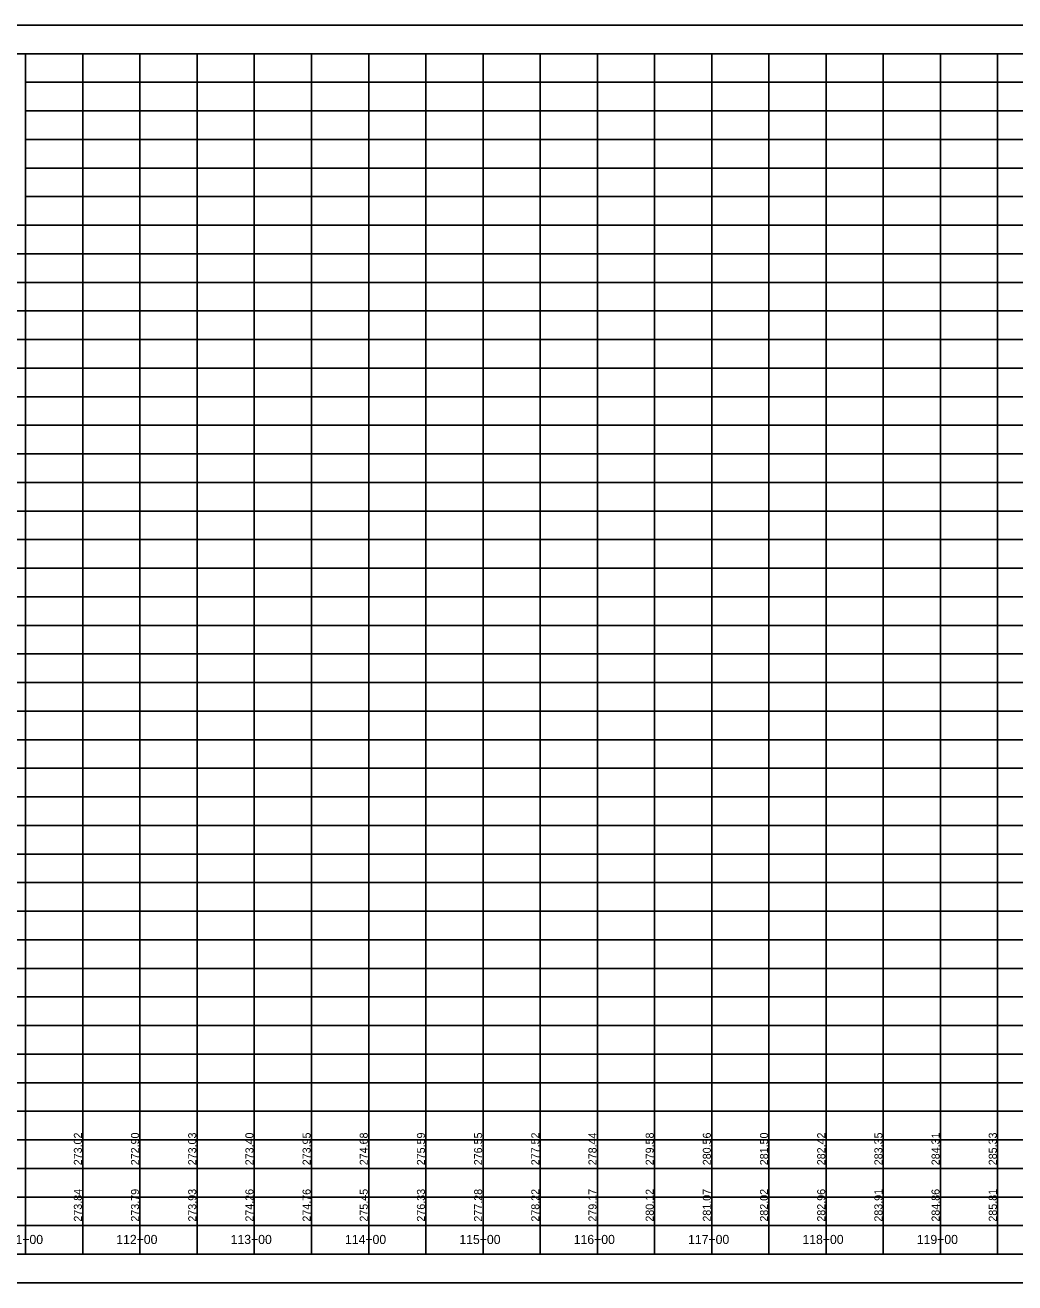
# Model space of a CAD drawing. Extents: x 1873632 to 1926512, y 813126 to 836257.
# Drawn here: x 1889463 to 1890328, y 828463 to 829563 of the extents above; entities that cross this region are included whole.
import ezdxf

# ---------------------------------------------------------------- set-up
doc = ezdxf.new("R2010")
doc.units = 0
for name, color, linetype in [('RD_DDB_StaTX', 7, 'Continuous'), ('RD_DDB_StripGrade', 7, 'Continuous'), ('RD_PD_WallFill', 7, 'Continuous'), ('RD_SHT_IplotShp', 7, 'Continuous')]:
    doc.layers.add(name, color=color, linetype=linetype)

msp = doc.modelspace()

# ---------------------------------------------------------------- linework, layer by layer
at = {"layer": 'RD_PD_WallFill'}
for p, q in [((1889012.9, 829538.1), (1894362.9, 829538.1)), ((1889012.9, 829538.1), (1890762.9, 829538.1)), ((1889462.9, 828488.1), (1889462.9, 829538.1)), ((1889462.9, 828488.1), (1889462.9, 829538.1)), ((1889512.9, 828488.1), (1889512.9, 829538.1)), ((1889512.9, 828488.1), (1889512.9, 829538.1)), ((1889562.9, 828488.1), (1889562.9, 829538.1)), ((1889562.9, 828488.1), (1889562.9, 829538.1)), ((1889612.9, 828488.1), (1889612.9, 829538.1)), ((1889612.9, 828488.1), (1889612.9, 829538.1)), ((1889662.9, 828488.1), (1889662.9, 829538.1)), ((1889662.9, 828488.1), (1889662.9, 829538.1)), ((1889712.9, 828488.1), (1889712.9, 829538.1)), ((1889712.9, 828488.1), (1889712.9, 829538.1)), ((1889762.9, 828488.1), (1889762.9, 829538.1)), ((1889762.9, 828488.1), (1889762.9, 829538.1)), ((1889812.9, 828488.1), (1889812.9, 829538.1)), ((1889812.9, 828488.1), (1889812.9, 829538.1)), ((1889862.9, 828488.1), (1889862.9, 829538.1)), ((1889862.9, 828488.1), (1889862.9, 829538.1)), ((1889912.9, 828488.1), (1889912.9, 829538.1)), ((1889912.9, 828488.1), (1889912.9, 829538.1)), ((1889962.9, 828488.1), (1889962.9, 829538.1)), ((1889962.9, 828488.1), (1889962.9, 829538.1)), ((1890012.9, 828488.1), (1890012.9, 829538.1)), ((1890012.9, 828488.1), (1890012.9, 829538.1)), ((1890062.9, 828488.1), (1890062.9, 829538.1)), ((1890062.9, 828488.1), (1890062.9, 829538.1)), ((1890112.9, 828488.1), (1890112.9, 829538.1)), ((1890112.9, 828488.1), (1890112.9, 829538.1)), ((1890162.9, 828488.1), (1890162.9, 829538.1)), ((1890162.9, 828488.1), (1890162.9, 829538.1)), ((1890212.9, 828488.1), (1890212.9, 829538.1)), ((1890212.9, 828488.1), (1890212.9, 829538.1)), ((1890262.9, 828488.1), (1890262.9, 829538.1)), ((1890262.9, 828488.1), (1890262.9, 829538.1)), ((1890312.9, 828488.1), (1890312.9, 829538.1)), ((1890312.9, 828488.1), (1890312.9, 829538.1)), ((1889462.9, 829513.1), (1894362.9, 829513.1)), ((1889462.9, 829513.1), (1894362.9, 829513.1)), ((1889462.9, 829488.1), (1894362.9, 829488.1)), ((1889462.9, 829463.1), (1894362.9, 829463.1)), ((1889462.9, 829438.1), (1894362.9, 829438.1)), ((1889462.9, 829413.1), (1894362.9, 829413.1)), ((1889012.9, 829388.1), (1894362.9, 829388.1)), ((1889012.9, 829363.1), (1894362.9, 829363.1)), ((1889012.9, 829338.1), (1894362.9, 829338.1)), ((1889012.9, 829313.1), (1894362.9, 829313.1)), ((1889012.9, 829288.1), (1894362.9, 829288.1)), ((1889012.9, 829263.1), (1894362.9, 829263.1)), ((1889012.9, 829238.1), (1894362.9, 829238.1)), ((1889012.9, 829213.1), (1894362.9, 829213.1)), ((1889012.9, 829188.1), (1894362.9, 829188.1)), ((1889012.9, 829163.1), (1894362.9, 829163.1)), ((1889012.9, 829138.1), (1894362.9, 829138.1)), ((1889012.9, 829113.1), (1894362.9, 829113.1)), ((1889012.9, 829088.1), (1894362.9, 829088.1)), ((1889012.9, 829063.1), (1894362.9, 829063.1)), ((1889012.9, 829038.1), (1894362.9, 829038.1)), ((1889012.9, 829013.1), (1894362.9, 829013.1)), ((1889012.9, 828988.1), (1894362.9, 828988.1)), ((1889012.9, 828963.1), (1894362.9, 828963.1)), ((1889012.9, 828938.1), (1894362.9, 828938.1)), ((1889012.9, 828913.1), (1894362.9, 828913.1)), ((1889012.9, 828888.1), (1894362.9, 828888.1)), ((1889012.9, 828863.1), (1894362.9, 828863.1)), ((1889012.9, 828838.1), (1894362.9, 828838.1)), ((1889012.9, 828813.1), (1894362.9, 828813.1)), ((1889012.9, 828788.1), (1894362.9, 828788.1)), ((1889012.9, 828763.1), (1894362.9, 828763.1)), ((1889012.9, 828738.1), (1894362.9, 828738.1)), ((1889012.9, 828713.1), (1894362.9, 828713.1)), ((1889012.9, 828688.1), (1894362.9, 828688.1)), ((1889012.9, 828663.1), (1894362.9, 828663.1)), ((1889012.9, 828638.1), (1894362.9, 828638.1)), ((1889012.9, 828613.1), (1894362.9, 828613.1)), ((1889012.9, 828588.1), (1894362.9, 828588.1)), ((1889012.9, 828563.1), (1894362.9, 828563.1)), ((1889012.9, 828538.1), (1894362.9, 828538.1)), ((1889012.9, 828513.1), (1894362.9, 828513.1)), ((1889012.9, 828488.1), (1894362.9, 828488.1)), ((1889012.9, 828488.1), (1894362.9, 828488.1))]:
    msp.add_line(p, q, dxfattribs=at)
msp.add_lwpolyline([(1889062.9, 829538.1), (1889462.9, 829538.1), (1889462.9, 829388.1), (1889062.9, 829388.1)], close=True, dxfattribs=at)
msp.add_lwpolyline([(1889062.9, 829538.1), (1889462.9, 829538.1), (1889462.9, 829388.1), (1889062.9, 829388.1)], close=True, dxfattribs=at)
msp.add_lwpolyline([(1889062.9, 829538.1), (1889462.9, 829538.1), (1889462.9, 829388.1), (1889062.9, 829388.1)], close=True, dxfattribs=at)
msp.add_lwpolyline([(1889062.9, 829538.1), (1889462.9, 829538.1), (1889462.9, 829388.1), (1889062.9, 829388.1)], close=True, dxfattribs=at)
at = {"layer": 'RD_SHT_IplotShp'}
msp.add_lwpolyline([(1888987.8, 828463.1), (1894387.8, 828463.1), (1894387.8, 829563.1), (1888987.8, 829563.1)], close=True, dxfattribs=at)

# ---------------------------------------------------------------- texts
at = {"layer": 'RD_DDB_StaTX'}
for s, p in [('111+00', (1889442.2, 828497)), ('112+00', (1889542.2, 828497)), ('113+00', (1889642.2, 828497)), ('114+00', (1889742.2, 828497)), ('115+00', (1889842.2, 828497)), ('116+00', (1889942.2, 828497)), ('117+00', (1890042.2, 828497)), ('118+00', (1890142.2, 828497)), ('119+00', (1890242.2, 828497))]:
    msp.add_text(s, height=8, dxfattribs=at).set_placement(p)
at = {"layer": 'RD_DDB_StripGrade'}
for s, p in [('273.02', (1889512.1, 828565.9)), ('272.90', (1889562.1, 828565.9)), ('273.03', (1889612.1, 828565.9)), ('273.40', (1889662.1, 828565.9)), ('273.95', (1889712.1, 828565.9)), ('274.68', (1889762.1, 828565.9)), ('275.59', (1889812.1, 828565.9)), ('276.55', (1889862.1, 828565.9)), ('277.52', (1889912.1, 828565.9)), ('278.44', (1889962.1, 828565.9)), ('279.58', (1890012.1, 828565.9)), ('280.56', (1890062.1, 828565.9)), ('281.50', (1890112.1, 828565.9)), ('282.42', (1890162.1, 828565.9)), ('283.35', (1890212.1, 828565.9)), ('284.31', (1890262.1, 828565.9)), ('285.33', (1890312.1, 828565.9)), ('273.84', (1889512.1, 828516.6)), ('273.79', (1889562.1, 828516.6)), ('273.93', (1889612.1, 828516.6)), ('274.26', (1889662.1, 828516.6)), ('274.76', (1889712.1, 828516.6)), ('275.45', (1889762.1, 828516.6)), ('276.33', (1889812.1, 828516.6)), ('277.28', (1889862.1, 828516.6)), ('278.22', (1889912.1, 828516.6)), ('279.17', (1889962.1, 828516.6)), ('280.12', (1890012.1, 828516.6)), ('281.07', (1890062.1, 828516.6)), ('282.02', (1890112.1, 828516.6)), ('282.96', (1890162.1, 828516.6)), ('283.91', (1890212.1, 828516.6)), ('284.86', (1890262.1, 828516.6)), ('285.81', (1890312.1, 828516.6))]:
    msp.add_text(s, height=7, rotation=90, dxfattribs=at).set_placement(p)

doc.saveas('drawing.dxf')
